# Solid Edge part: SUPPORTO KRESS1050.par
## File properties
Subject: SUPPORTO KRESS1050
Author: f_grande
Template: Normal.par
Last saved by: f_grande
Revision: 15
Application: Solid Edge
Material: Alluminio, 1060
Stile della faccia: Alluminio
Stile di riempimento: ANSI38(Alluminio)
Stile virtuale: Alluminio lucidato
Coef. of Thermal Exp: 0.0
Thermal Conductivity: 221.0
Specific Heat: 920.0
Modulus of Elasticity: 68947570000.0
Poisson's Ratio: 0.33
Yield Stress: 27579028.0
Ultimate Stress: 68947570.0
Elongation: 0.0
Tipo di contenuto documento: 0
Densità: 2712,000 kg/m^3
Precisione: 0,990
Document Number: KR0141
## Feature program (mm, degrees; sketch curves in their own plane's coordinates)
sketch for "unnamed Protrusion 1" plane through (0, 0, 0) normal (0, 0, 1) x-axis (1, 0, 0)
  line (-47.5, 39) -> (47.5, 39)
  line (47.5, 39) -> (47.5, -39)
  line (47.5, -39) -> (-47.5, -39)
  line (-47.5, -39) -> (-47.5, 39)
  dimension (linear) = 47.5
  dimension (linear) = 47.5
extrude "unnamed Protrusion 1" add finite 19 along +normal
sketch for "unnamed Cutout 1" #1 plane through (27.7854, -6.6337, 19) normal (0, 0, 1) x-axis (1, 0, 0)
sketch for "unnamed Cutout 1" #2 plane through (27.7854, -6.6337, 19) normal (0, 0, 1) x-axis (1, 0, 0)
  line (-57.2854, -32.3663) -> (-57.2854, 17.6337)
  line (-57.2854, 17.6337) -> (-75.2854, 17.6337)
  line (-75.2854, 17.6337) -> (-75.2854, -32.3663)
  line (-75.2854, -32.3663) -> (-57.2854, -32.3663)
  dimension (linear) = 75.2854
  dimension (linear) = 75.2854
extrude "unnamed Cutout 1" cut to key point along -normal
fillet "Rotondo_1" radius 7
chamfer "Smusso_1" setback 2
sketch for "Foro_5" plane through (11.7854, -5.6337, 19) normal (0, 0, 1) x-axis (1, 0, 0)
  hole centre (-11.7854, 3.9837) bore radius 21.5
hole "Foro_5" diameter 43 through
sketch for "Foro_6" plane through (-29.7146, 11, 9.5) normal (0, -1, 0) x-axis (1, 0, 0)
hole "Foro_6" diameter 6.5 through
sketch for "unnamed Hole 1" plane through (-29.7146, 11, 9.5) normal (0, -1, 0) x-axis (1, 0, 0)
hole "unnamed Hole 1" through
pattern "unnamed Pattern 1" of "Foro_6", "unnamed Hole 1"
sketch for "ExtrudedCutout_2" plane through (11.7854, -5.6337, 19) normal (0, 0, 1) x-axis (1, 0, 0)
extrude "ExtrudedCutout_2" cut finite 40.5503 along -normal
sketch for "Foro_8" plane through (29.5, -22.1337, 9.5) normal (1, 0, 0) x-axis (0, 1, 0)
hole "Foro_8" diameter 6 finite
thread "unnamed Thread 1"
sketch for "ExtrudedCutout_3" plane through (29.5, -22.1337, 9.5) normal (1, 0, 0) x-axis (0, 1, 0)
extrude "ExtrudedCutout_3" cut finite 7 along -normal
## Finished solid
Body 1: solid body, 27 faces, 64 edges, 36 vertices.
  Faces by surface: plane 19, cylinder 8
  Edges by curve: line 48, circle 16
Bounding box of the edges (mm): 95.000 x 78.000 x 19.000, from (-47.5, -39, 0) to (47.5, 39, 19).
Cylindrical faces by radius (mm): R3 x2, R3.25 x2, R5 x1, R7 x2, R21.5 x1
Planar faces by outward normal: +x 5, +y 1, +z 1, -x 3, -y 4, -z 1, oblique 4
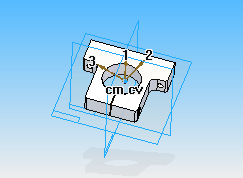
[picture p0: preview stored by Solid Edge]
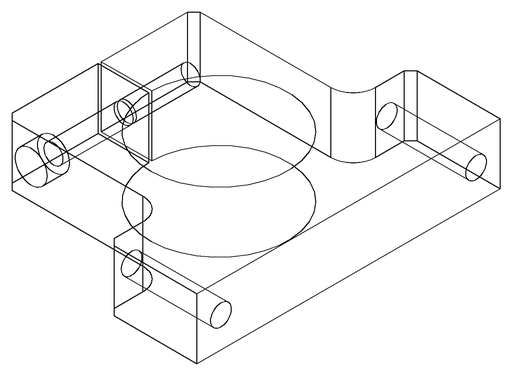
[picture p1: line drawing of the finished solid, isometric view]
